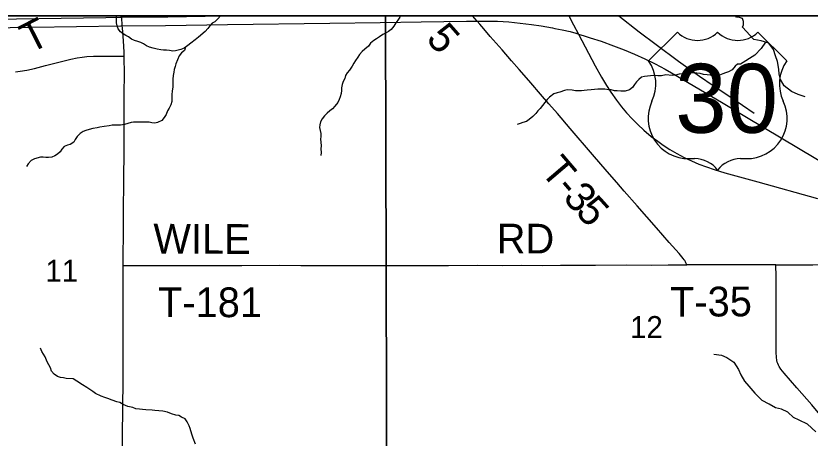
# Model space of a CAD drawing. Extents: x 0 to 34, y 0 to 22.
# Drawn here: x 3.95 to 5.466, y 20.093 to 20.9 of the extents above; entities that cross this region are included whole.
import ezdxf

# ---------------------------------------------------------------- set-up
doc = ezdxf.new("R2010")
doc.units = 0
for name, color, linetype in [('Default', 7, 'Continuous'), ('GM_X_County_Road', 7, 'Continuous'), ('GM_X_Minor_River', 7, 'Continuous'), ('GM_X_Section_Text', 7, 'Continuous'), ('GM_X_State_Route', 7, 'Continuous'), ('GM_X_Township_Road', 7, 'Continuous'), ('GM_X_Township_Road_Text', 7, 'Continuous'), ('GM_X_US_Location', 7, 'Continuous'), ('GM_X_US_Route', 7, 'Continuous'), ('GM_X_US_Shield', 7, 'Continuous'), ('SH_Data', 7, 'Continuous')]:
    doc.layers.add(name, color=color, linetype=linetype)

msp = doc.modelspace()

# ---------------------------------------------------------------- linework, layer by layer
at = {"layer": 'Default'}
for points in [[(4.655, 20.9), (3.6554, 20.9), (3.6434, 19.919), (4.6576, 19.9182)], [(5.6501, 20.9), (4.655, 20.9), (4.6576, 19.9182), (5.654, 19.9264)]]:
    msp.add_lwpolyline(points, close=True, dxfattribs=at)
at = {"layer": 'GM_X_County_Road'}
for points in [[(4.1527, 20.8807), (4.1519, 20.8972), (4.1519, 20.8989), (4.1518, 20.9)], [(4.1563, 20.8229), (4.1561, 20.8306), (4.1549, 20.8523), (4.1529, 20.8771), (4.1527, 20.8807)], [(3.9486, 20.7929), (3.9578, 20.7941), (3.9705, 20.7964), (3.9853, 20.7996), (4.0064, 20.8051), (4.0366, 20.8128), (4.0547, 20.8175), (4.0668, 20.8199), (4.076, 20.8212), (4.0852, 20.822), (4.0975, 20.8227), (4.1161, 20.8229), (4.1348, 20.8228), (4.1535, 20.8228), (4.1563, 20.8229)], [(4.1567, 20.798), (4.1566, 20.8119), (4.1563, 20.8229)], [(4.1547, 20.4232), (4.1547, 20.4298), (4.1552, 20.495), (4.1551, 20.523), (4.1555, 20.5882), (4.156, 20.641), (4.1561, 20.6939), (4.1565, 20.7529), (4.1567, 20.7871), (4.1567, 20.798)], [(4.1527, 19.9174), (4.1527, 19.9328), (4.1528, 19.9514), (4.1527, 19.97), (4.1529, 19.9886), (4.1533, 20.057), (4.1533, 20.116), (4.1535, 20.1316), (4.1538, 20.1564), (4.1542, 20.1968), (4.1543, 20.2217), (4.1542, 20.2558), (4.1542, 20.2962), (4.1546, 20.3801), (4.1547, 20.4019), (4.1547, 20.4232)]]:
    msp.add_lwpolyline(points, dxfattribs=at)
at = {"layer": 'GM_X_Minor_River'}
for points in [[(4.3402, 20.9), (4.3354, 20.8945), (4.3294, 20.8884), (4.3244, 20.8857), (4.3199, 20.8807), (4.3161, 20.8758), (4.3112, 20.8704), (4.298, 20.859), (4.2916, 20.854), (4.2836, 20.8479), (4.2776, 20.8433), (4.2708, 20.8383), (4.2644, 20.8356), (4.2594, 20.8345), (4.2541, 20.8333), (4.2492, 20.8325), (4.2427, 20.8336), (4.237, 20.8343), (4.2313, 20.8343), (4.2264, 20.8351), (4.2192, 20.8365), (4.2116, 20.8384), (4.2047, 20.8403), (4.199, 20.8425), (4.193, 20.8463), (4.188, 20.8493), (4.1823, 20.8512), (4.1758, 20.8531), (4.1705, 20.8553), (4.1648, 20.8599), (4.1595, 20.8625), (4.1545, 20.8655), (4.1492, 20.8693), (4.145, 20.8754), (4.1431, 20.8807), (4.1419, 20.8864), (4.1418, 20.8947), (4.1415, 20.9)], [(4.6838, 20.9), (4.6826, 20.8976), (4.6785, 20.8919), (4.6751, 20.8869), (4.671, 20.8801), (4.6661, 20.8736), (4.6611, 20.8701), (4.6562, 20.8678), (4.6502, 20.8644), (4.6437, 20.8602), (4.6381, 20.8563), (4.6328, 20.8529), (4.6267, 20.8475), (4.6226, 20.8422), (4.6158, 20.8361), (4.6109, 20.8319), (4.6056, 20.8261), (4.6022, 20.8212), (4.5981, 20.8147), (4.5947, 20.8098), (4.5913, 20.804), (4.5864, 20.7964), (4.5822, 20.7911), (4.5789, 20.7861), (4.5774, 20.7804), (4.5744, 20.7743), (4.5725, 20.769), (4.5714, 20.7625), (4.571, 20.7576), (4.5703, 20.7518), (4.5688, 20.745), (4.5669, 20.74), (4.5639, 20.7347), (4.5587, 20.7275), (4.5541, 20.7225), (4.5492, 20.7183), (4.5439, 20.7141), (4.5386, 20.7091), (4.5341, 20.7034), (4.5311, 20.6973), (4.5296, 20.6916), (4.5293, 20.6866), (4.5308, 20.6806), (4.5316, 20.6752), (4.5316, 20.6695), (4.5313, 20.6642), (4.5317, 20.6585), (4.5321, 20.6517), (4.5318, 20.6456), (4.5322, 20.6388), (4.5318, 20.633)], [(5.3584, 20.855), (5.337, 20.8782), (5.3385, 20.8831), (5.3389, 20.8892), (5.3369, 20.8949), (5.3309, 20.8968), (5.3255, 20.8975), (5.3232, 20.9)], [(5.4564, 20.745), (5.4428, 20.7494), (5.4302, 20.7554), (5.4162, 20.7663), (5.4093, 20.7784), (5.4065, 20.7886), (5.4061, 20.7981), (5.4037, 20.8128), (5.3999, 20.8234), (5.396, 20.8355), (5.3868, 20.8476), (5.3724, 20.8524), (5.3584, 20.855)], [(5.3806, 20.8497), (5.3721, 20.8373), (5.3601, 20.8246)], [(4.2732, 20.8401), (4.2712, 20.8337), (4.2655, 20.8292), (4.2614, 20.8234), (4.258, 20.8162), (4.255, 20.8082), (4.2535, 20.8032), (4.252, 20.7975), (4.2509, 20.7926), (4.2498, 20.7857), (4.2495, 20.7789), (4.2495, 20.7721), (4.2492, 20.7641), (4.2481, 20.7561), (4.2473, 20.7496), (4.2474, 20.7435), (4.2474, 20.7363), (4.2456, 20.7302), (4.2422, 20.7234), (4.2392, 20.7184), (4.2365, 20.7115), (4.2328, 20.7058), (4.2279, 20.7001), (4.2199, 20.6963), (4.2146, 20.6951), (4.2093, 20.6958), (4.204, 20.6969), (4.1793, 20.6968), (4.1744, 20.6968), (4.1694, 20.696), (4.163, 20.6945), (4.1569, 20.6922), (4.149, 20.691), (4.1418, 20.6913), (4.1334, 20.6909), (4.1274, 20.6901), (4.1179, 20.6886), (4.1099, 20.6874), (4.105, 20.6862), (4.0966, 20.6847), (4.0898, 20.6831), (4.083, 20.6812), (4.0781, 20.6793), (4.072, 20.675), (4.0664, 20.6693), (4.063, 20.6636), (4.06, 20.6583), (4.0532, 20.6541), (4.0482, 20.6529), (4.0418, 20.6506), (4.0373, 20.6452), (4.0343, 20.6403), (4.0293, 20.6357), (4.024, 20.6322), (4.018, 20.6299), (4.0119, 20.6291), (4.007, 20.6295), (4.0017, 20.6302), (3.9964, 20.6298), (3.985, 20.6267), (3.9786, 20.6237), (3.9729, 20.6172), (3.9699, 20.6122)], [(5.3601, 20.8246), (5.3332, 20.8074), (5.3275, 20.8074), (5.3226, 20.804), (5.3173, 20.7971), (5.3101, 20.7932), (5.3045, 20.7909), (5.2992, 20.7894), (5.2931, 20.7867), (5.2866, 20.7859), (5.2806, 20.7859), (5.2749, 20.7866), (5.2696, 20.787), (5.2623, 20.7881), (5.2559, 20.79), (5.2498, 20.7907), (5.243, 20.7914), (5.2361, 20.7906), (5.2274, 20.7894), (5.2217, 20.789), (5.2157, 20.7883), (5.2088, 20.7867), (5.2024, 20.7859), (5.1902, 20.7874), (5.1819, 20.7854), (5.1751, 20.7854), (5.1679, 20.7858), (5.1614, 20.7853), (5.1557, 20.7849), (5.1497, 20.7842), (5.144, 20.783), (5.1391, 20.7784), (5.1341, 20.7742), (5.1304, 20.7689), (5.127, 20.7628), (5.1209, 20.7589), (5.113, 20.7562), (5.1046, 20.7558), (5.0978, 20.7565), (5.0925, 20.7569), (5.086, 20.7584), (5.0811, 20.7587), (5.0739, 20.7599), (5.0674, 20.7602), (5.0606, 20.7598), (5.0541, 20.7594), (5.0477, 20.7586), (5.0405, 20.7582), (5.0348, 20.7574), (5.0295, 20.757), (5.0177, 20.7569), (5.0113, 20.7577), (5.0022, 20.7584), (4.9968, 20.7576), (4.9878, 20.7541), (4.9828, 20.753), (4.9764, 20.7507), (4.9681, 20.7449), (4.9639, 20.74), (4.9594, 20.7342), (4.9552, 20.7289), (4.9503, 20.7232), (4.9462, 20.7182), (4.9424, 20.7132), (4.9368, 20.7075), (4.9292, 20.7018), (4.9243, 20.6983), (4.9175, 20.696), (4.9122, 20.6941), (4.9065, 20.6926)], [(4.0052, 20.2485), (3.9994, 20.2588), (3.9964, 20.2652)], [(4.2922, 20.0814), (4.288, 20.0932), (4.2857, 20.1004), (4.2822, 20.1114), (4.2806, 20.1163), (4.2764, 20.1243), (4.273, 20.13), (4.2658, 20.1334), (4.2608, 20.136), (4.2551, 20.1371), (4.2464, 20.1397), (4.2388, 20.1428), (4.2304, 20.1446), (4.2148, 20.1461), (4.2095, 20.1468), (4.1978, 20.1471), (4.1913, 20.1479), (4.1856, 20.1482), (4.1788, 20.1489), (4.1731, 20.1516), (4.1632, 20.1534), (4.1541, 20.1576), (4.148, 20.161), (4.1426, 20.1621), (4.1331, 20.1655), (4.1252, 20.1685), (4.1194, 20.1707), (4.1126, 20.1734), (4.1016, 20.1786), (4.0962, 20.1824), (4.0848, 20.1896), (4.0768, 20.1952), (4.0662, 20.202), (4.0589, 20.2062), (4.0453, 20.2073), (4.0403, 20.208), (4.035, 20.2087), (4.0293, 20.211), (4.0228, 20.2151), (4.0175, 20.2208), (4.0155, 20.2273), (4.0094, 20.2387), (4.0052, 20.2485)], [(5.2822, 20.2536), (5.2966, 20.2514), (5.3068, 20.2473), (5.3201, 20.2379), (5.3293, 20.2243), (5.3335, 20.2141), (5.3404, 20.202), (5.3488, 20.1922), (5.3602, 20.1789)], [(5.4768, 20.105), (5.4611, 20.12), (5.4452, 20.1275), (5.4342, 20.1323), (5.4231, 20.1429), (5.411, 20.1485), (5.4, 20.151), (5.3874, 20.1578), (5.3741, 20.1649), (5.3602, 20.1789)]]:
    msp.add_lwpolyline(points, dxfattribs=at)
at = {"layer": 'GM_X_State_Route'}
msp.add_lwpolyline([(5.6507, 20.9), (2.1, 20.9)], dxfattribs=at)
at = {"layer": 'GM_X_Township_Road'}
msp.add_line((4.8299, 20.8901), (4.8216, 20.9), dxfattribs=at)
for points in [[(5.2307, 20.4239), (5.2288, 20.4283), (5.2281, 20.4299), (5.2274, 20.4314), (5.2265, 20.4328), (5.2257, 20.434), (5.2238, 20.4364), (5.2156, 20.4458), (5.1969, 20.4667), (5.1724, 20.4947), (5.1356, 20.5368), (5.1111, 20.5649), (5.0968, 20.5813), (5.0785, 20.6024), (5.0502, 20.6353), (5.0079, 20.685), (4.9836, 20.7133), (4.9672, 20.7319), (4.9549, 20.7459), (4.9287, 20.7766), (4.9103, 20.7976), (4.896, 20.814), (4.8777, 20.8351), (4.8553, 20.8608), (4.8432, 20.875), (4.835, 20.8844), (4.8299, 20.8901)], [(5.4002, 20.4244), (5.3814, 20.4242), (5.3593, 20.4241), (5.3158, 20.424), (5.2755, 20.4241), (5.2413, 20.4239), (5.2307, 20.4239)], [(5.4002, 20.4244), (5.4061, 20.4244), (5.4243, 20.4243), (5.4426, 20.4241), (5.4708, 20.4244), (5.4885, 20.4246), (5.5086, 20.4247), (5.5125, 20.4247)], [(5.4843, 20.138), (5.4689, 20.1564), (5.4406, 20.1894), (5.416, 20.2175), (5.4102, 20.2247), (5.4067, 20.2299), (5.4052, 20.2326), (5.404, 20.2355), (5.403, 20.2384), (5.4023, 20.2414), (5.4014, 20.2476), (5.401, 20.2569), (5.4011, 20.2973), (5.4012, 20.3377), (5.4012, 20.3843), (5.4011, 20.4091), (5.4006, 20.4175), (5.4003, 20.4226), (5.4002, 20.4244)], [(4.1547, 20.4232), (4.1589, 20.4232), (4.1658, 20.4232), (4.1923, 20.4231), (4.2356, 20.4231), (4.2741, 20.4231), (4.3092, 20.4232), (4.3487, 20.4232), (4.3807, 20.423), (4.4519, 20.4233), (4.4936, 20.4232), (4.5476, 20.4227), (4.5818, 20.4227), (4.6288, 20.4227), (4.6901, 20.4231)], [(4.6901, 20.4231), (4.6911, 20.4231), (4.7326, 20.4231), (4.7756, 20.4228), (4.8313, 20.4233), (4.8778, 20.4232), (4.9151, 20.4233), (4.9554, 20.4232), (4.9896, 20.4236), (5.0144, 20.4234), (5.0559, 20.4235), (5.116, 20.424), (5.1633, 20.4238), (5.1947, 20.4239), (5.2307, 20.4239)]]:
    msp.add_lwpolyline(points, dxfattribs=at)
at = {"layer": 'GM_X_US_Route'}
msp.add_line((5.0051, 20.9), (5.0057, 20.8987), dxfattribs=at)
for points in [[(3.8327, 20.8926), (3.9508, 20.8943), (4.1216, 20.8968), (4.1495, 20.8972), (4.1519, 20.8972), (4.2397, 20.8984), (4.3463, 20.9)], [(5.0057, 20.8987), (5.0143, 20.8827), (5.0237, 20.8653), (5.0558, 20.8047), (5.0678, 20.783), (5.0773, 20.767), (5.0856, 20.7539), (5.0962, 20.7386), (5.1056, 20.7263), (5.1156, 20.7145), (5.126, 20.703), (5.137, 20.6921), (5.1484, 20.6817), (5.1627, 20.6697), (5.175, 20.6603), (5.1851, 20.6531), (5.198, 20.6446), (5.2114, 20.6368), (5.2251, 20.6295), (5.2391, 20.6229), (5.2533, 20.6168), (5.2678, 20.6114), (5.2825, 20.6064), (5.3033, 20.6001), (5.3661, 20.5825), (5.4798, 20.5508)], [(5.1006, 20.9), (5.1395, 20.8695), (5.1718, 20.845), (5.2144, 20.8135), (5.2549, 20.7845), (5.2806, 20.7668), (5.3148, 20.7443), (5.3591, 20.7139)], [(3.8531, 20.8766), (3.9805, 20.8784), (4.1502, 20.8807), (4.1527, 20.8807), (4.2352, 20.8818), (4.3533, 20.8835), (4.549, 20.8863), (4.6453, 20.8875), (4.723, 20.8886), (4.81, 20.8901), (4.8299, 20.8901), (4.8314, 20.8901), (4.8473, 20.8901), (4.8691, 20.8896), (4.8908, 20.8883), (4.9125, 20.8863), (4.9341, 20.8837), (4.9526, 20.8809), (4.974, 20.877), (4.9788, 20.8761)], [(4.9788, 20.8761), (4.9923, 20.8733), (5.0075, 20.8698), (5.0186, 20.8668)], [(5.0186, 20.8668), (5.0195, 20.8666), (5.0237, 20.8653), (5.0343, 20.8619), (5.0461, 20.858), (5.0668, 20.8513), (5.0903, 20.843), (5.1106, 20.8352), (5.1307, 20.8267), (5.1505, 20.8177), (5.17, 20.8081), (5.1893, 20.7979), (5.2136, 20.7842), (5.2966, 20.7351), (5.3446, 20.7064), (5.5101, 20.6079), (5.5635, 20.576), (5.6224, 20.5414), (5.6468, 20.5277), (5.6508, 20.5255)]]:
    msp.add_lwpolyline(points, dxfattribs=at)
at = {"layer": 'GM_X_US_Shield'}
for p, q in [((5.2124, 20.8688), (5.1575, 20.8139)), ((5.4211, 20.8139), (5.3662, 20.8688)), ((5.2344, 20.6271), (5.2454, 20.6271)), ((5.3332, 20.6271), (5.3442, 20.6271))]:
    msp.add_line(p, q, dxfattribs=at)
for centre, radius, start, end in [((5.2508, 20.908), 0.0549, 225.573, 314.427), ((5.3277, 20.908), 0.0549, 225.573, 314.427), ((5.0945, 20.7698), 0.0769, 334.5471, 35.0009), ((5.4841, 20.7698), 0.0769, 144.9991, 205.4529), ((5.2335, 20.704), 0.0769, 154.8319, 270.6383), ((5.3451, 20.704), 0.0769, 269.3617, 25.1681), ((5.2454, 20.5722), 0.0549, 36.8699, 90), ((5.3332, 20.5722), 0.0549, 90, 143.1301)]:
    msp.add_arc(centre, radius, start, end, dxfattribs=at)
at = {"layer": 'SH_Data'}
msp.add_line((2.1, 20.9), (8.9, 20.9), dxfattribs=at)

# ---------------------------------------------------------------- texts
at = {"layer": 'GM_X_Section_Text'}
for s, p in [('11', (4.006, 20.392)), ('12', (5.1222, 20.2844))]:
    msp.add_text(s, height=0.04186, rotation=0, dxfattribs=at).set_placement(p)
at = {"layer": 'GM_X_Township_Road_Text'}
for s, height, rotation, p in [('T', 0.0568, 26.9445, (3.9766, 20.8273)), ('5', 0.0568, 311.3284, (4.7309, 20.855)), ('T', 0.0568, 310.4709, (4.9493, 20.6021)), ('-', 0.0568, 310.5362, (4.9769, 20.5697)), ('3', 0.0568, 310.8256, (4.9923, 20.5517)), ('5', 0.0568, 312.0874, (5.0161, 20.5242)), ('WILE', 0.05682, 359.7262, (4.2119, 20.4459)), ('RD', 0.05682, 0, (4.8676, 20.4459)), ('T-181', 0.05682, 0, (4.221, 20.3242)), ('T-35', 0.05682, 0.3529, (5.1986, 20.325))]:
    msp.add_text(s, height=height, rotation=rotation, dxfattribs=at).set_placement(p)
at = {"layer": 'GM_X_US_Location'}
for s in ['0', '/']:
    msp.add_text(s, height=0.000189, dxfattribs=at).set_placement((5.2892, 20.7414))
msp.add_text('30', height=0.000189, rotation=0, dxfattribs=at).set_placement((5.2501, 20.7022))
at = {"layer": 'GM_X_US_Shield'}
msp.add_text('30', height=0.13184, dxfattribs=at).set_placement((5.2084, 20.6765))

doc.saveas('drawing.dxf')
